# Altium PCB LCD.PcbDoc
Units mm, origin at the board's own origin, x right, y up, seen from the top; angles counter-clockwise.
Board outline 40 x 50 mm, 2 copper layers (Top Layer, Bottom Layer); 3 components, 29 nets, 23 pads, 0 vias.
Unrouted connection lines stored in the file: 1.
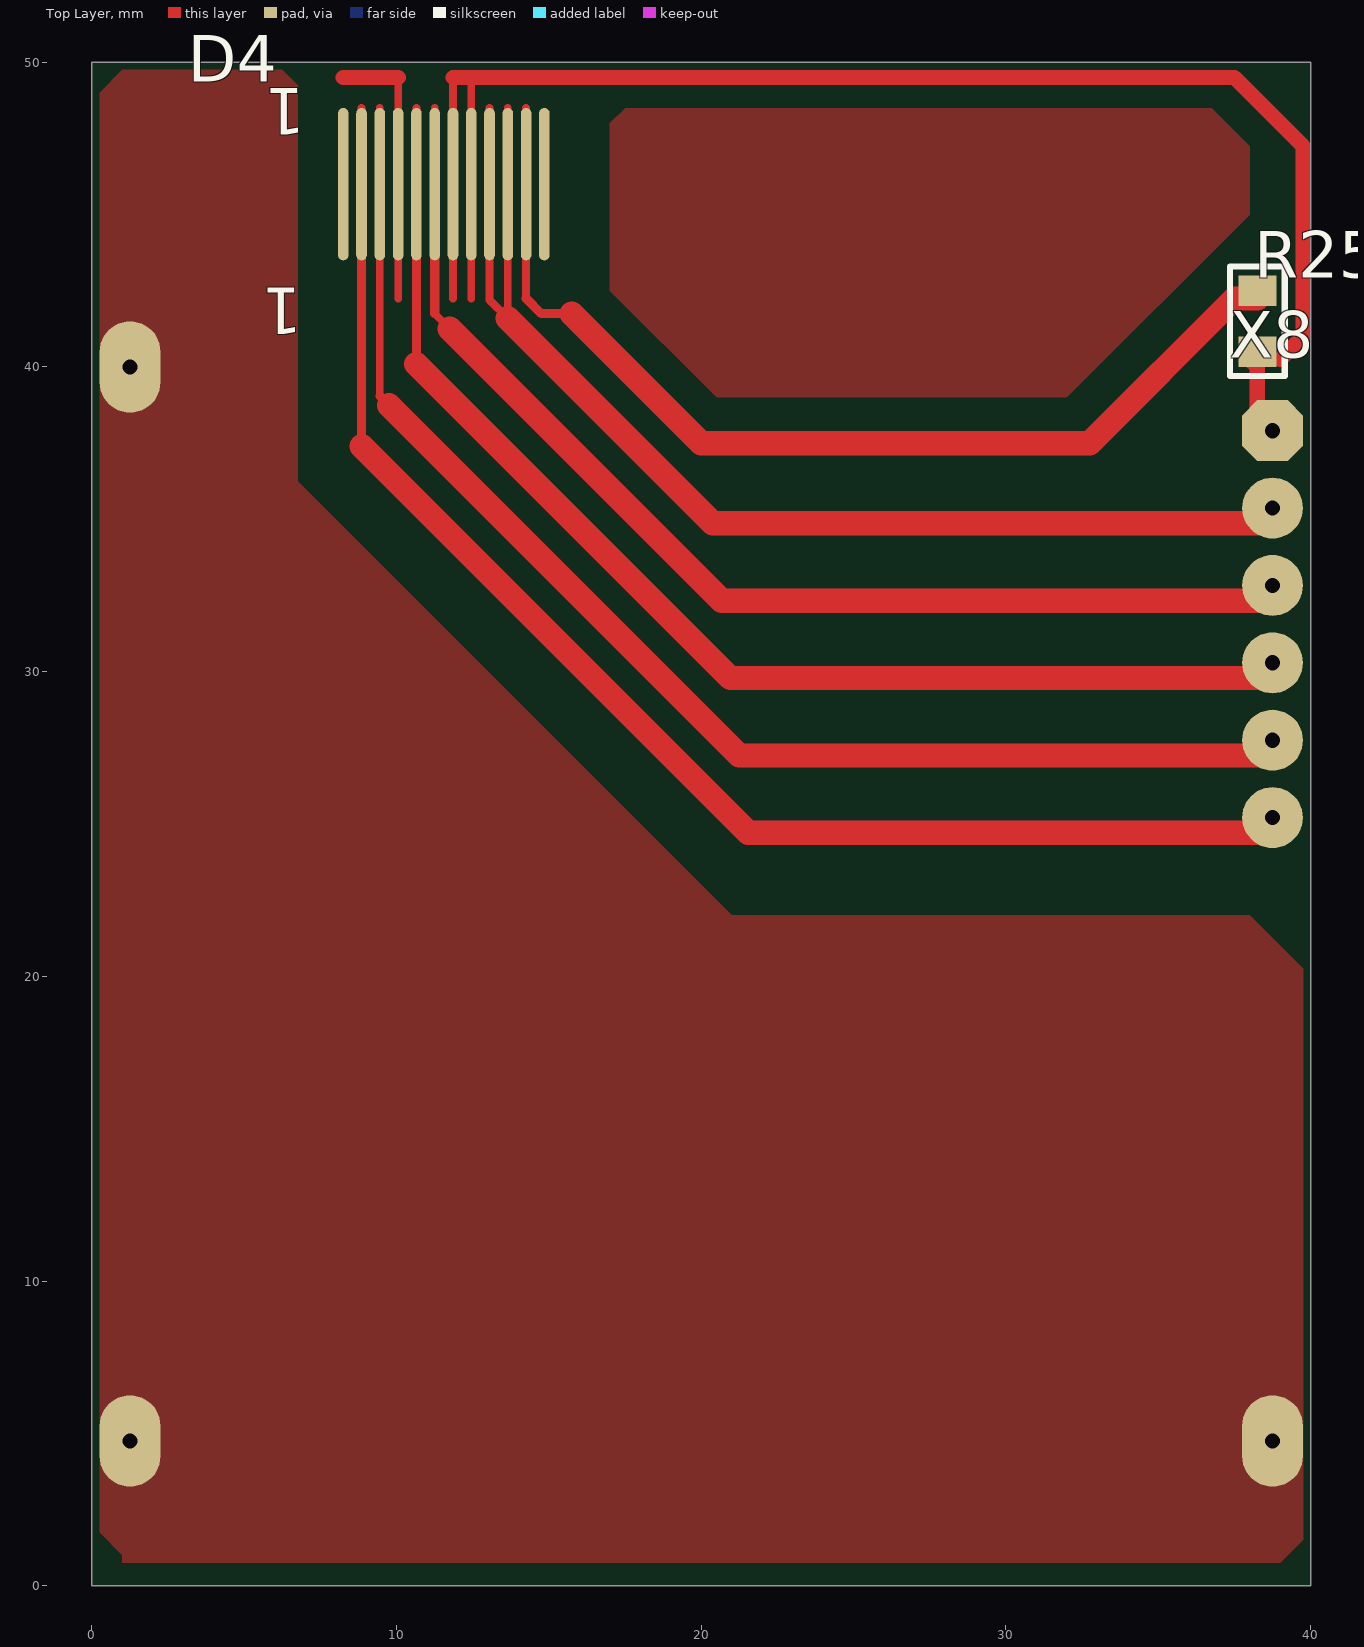
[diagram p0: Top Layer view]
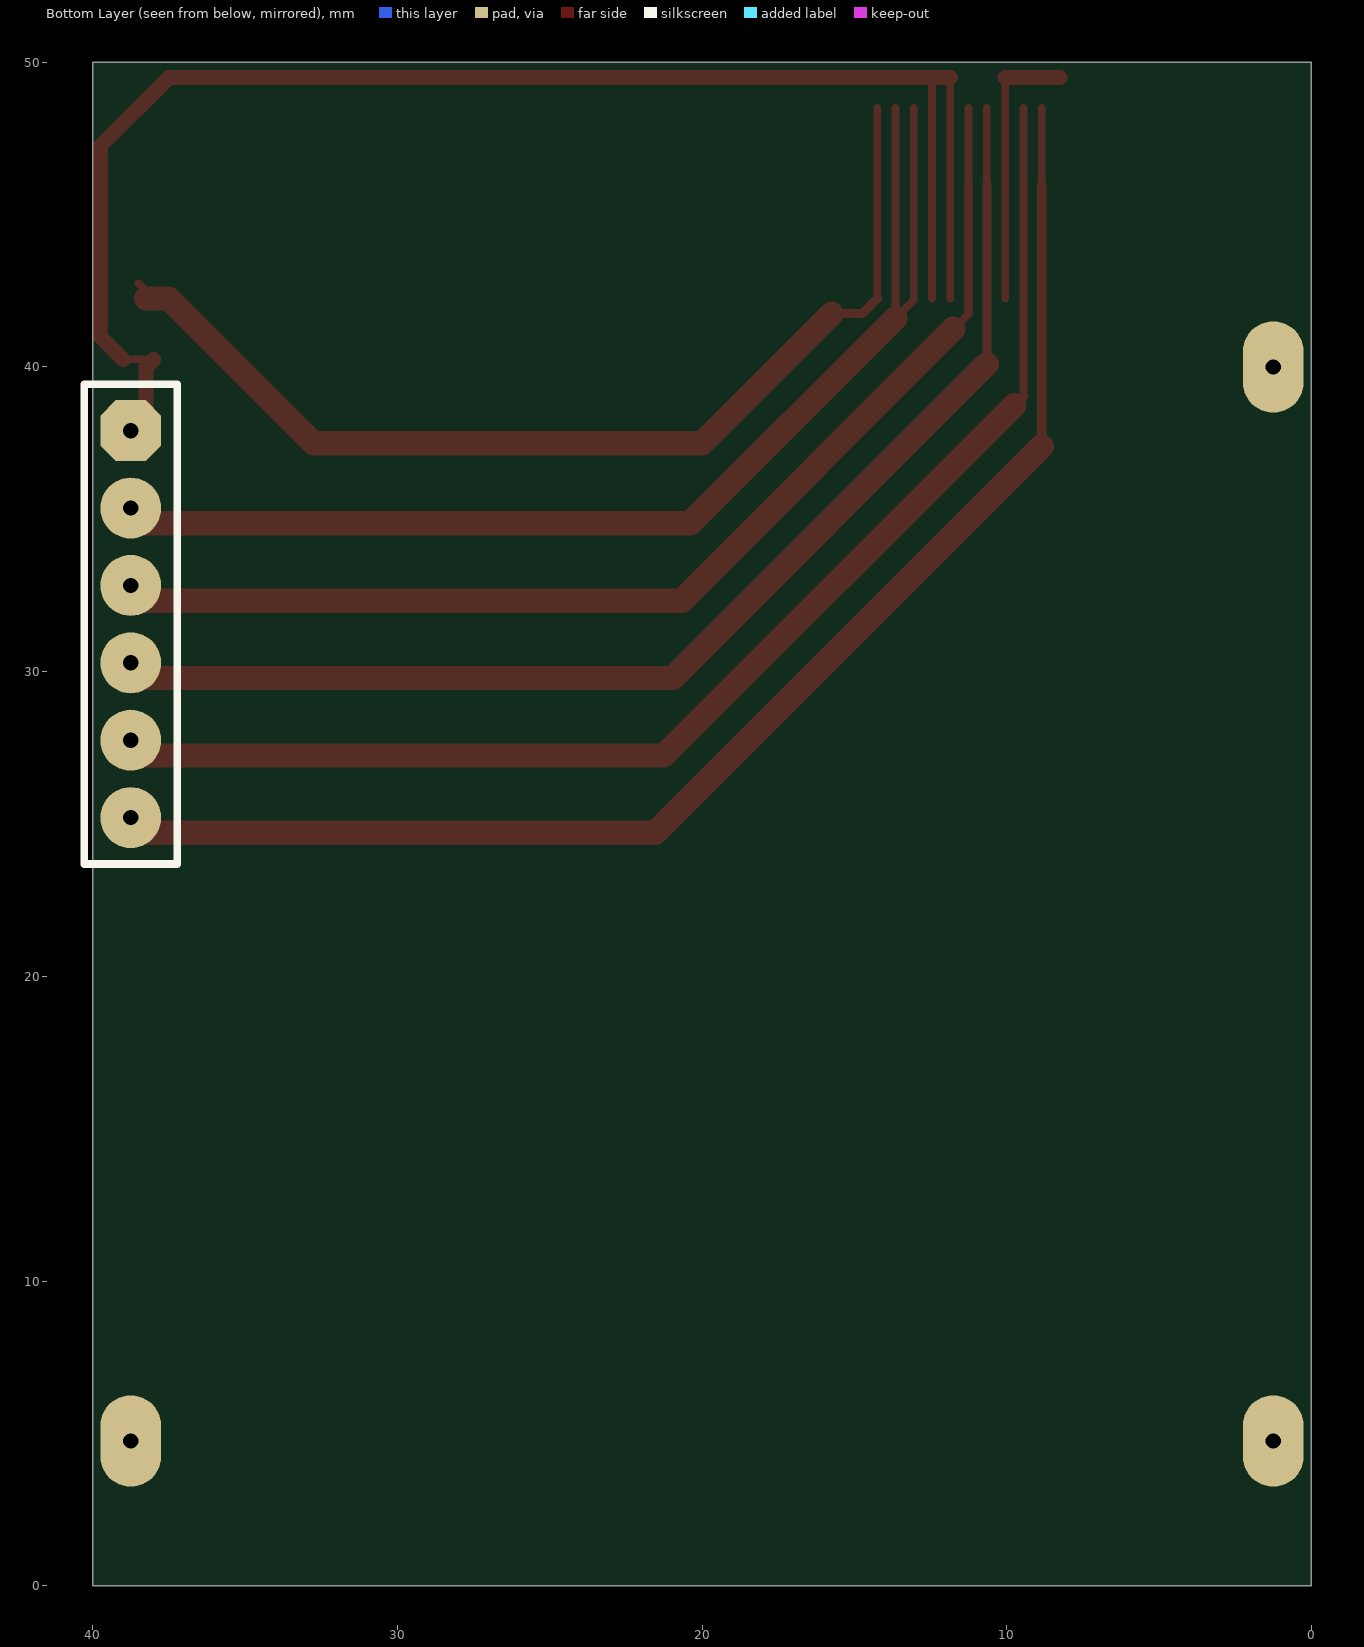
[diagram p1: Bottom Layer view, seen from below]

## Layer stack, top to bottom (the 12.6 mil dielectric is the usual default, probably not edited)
Top Solder: solder mask 0.0102, Solder Resist, Dk 3.5
Top Layer: signal copper 0.0356
Dielectric 1: dielectric 0.32, FR-4, Dk 4.8
Bottom Layer: signal copper 0.0356
Bottom Solder: solder mask 0.0102, Solder Resist, Dk 3.5

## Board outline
0,0 0,50 40,50 40,0

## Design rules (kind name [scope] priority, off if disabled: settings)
Clearance [All] p1: gap=0.1 ignorepadtopadclearanceinfootprint=FALSE
PolygonConnect [All] p1: connectstyle=Direct reliefconductorwidth=0.254 reliefentries=4 polygonreliefangle="90 Angle" airgapwidth=0.254
RoomDefinition LCD [InComponentClass('LCD')] p1: confinementstyle=ConfineIn formatcopy=TRUE lockcomponents=FALSE outline 40,30 90,30 90,100 40,100
RoutingVias [All] p1: holewidth=0.711 width=1.27 viastyle="Through Hole" minholewidth=0.711 minwidth=1.27 maxholewidth=0.711 maxwidth=1.27
SolderMaskExpansion [All] p1: expansion=0.102
Width [All] p1: maxlimit=1 minlimit=0.254 preferedwidth=0.4
30 further rules are at their usual default settings.

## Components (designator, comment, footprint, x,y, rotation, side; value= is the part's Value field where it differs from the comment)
D4 "Nokia_1616" LCD1616 20,43.5 r180 top
R25 "*" CH0805R 38.25,41.5 r90 top
X8 "*" "CON: PBS-6" 38.75,31.56 r270 top

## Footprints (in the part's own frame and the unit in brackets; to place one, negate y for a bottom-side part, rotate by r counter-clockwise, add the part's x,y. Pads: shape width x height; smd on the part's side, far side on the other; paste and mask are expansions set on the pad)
CH0805R [mm]
  rect 1x1.25 smd: 1(-1,0) 2(1,0)
  silkscreen extent -1.8,-0.9 1.8,0.9, body extent -1,-0.6 1,0.6, height 0.44
"CON: PBS-6" [mm] "PBS-6"
  oct 2x2 hole 0.5: 1(-6.35,0)
  round 2 hole 0.5: 2(-3.81,0) 3(-1.27,0) 4(1.27,0) 5(3.81,0) 6(6.35,0)
LCD1616 [mm] "LCD1616"
  oval 0.35x5 smd: 1(11.75,-2.5) 2(11.15,-2.5) 3(10.55,-2.5) 4(9.95,-2.5) 5(9.35,-2.5) 6(8.75,-2.5) 7(8.15,-2.5) 8(7.55,-2.5) 9(6.95,-2.5) 10(6.35,-2.5) 11(5.75,-2.5) 12(5.15,-2.5)
  body extent -17.1,-0.1 17.1,50.1, height 2

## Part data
D4: "MT10-T7"
R25: library part Resistor
X8: library part 6-Connector

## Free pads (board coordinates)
  oval 2x3 hole 0.5: 5(1.25,4.75) 5(1.25,40) 5(38.75,4.75)

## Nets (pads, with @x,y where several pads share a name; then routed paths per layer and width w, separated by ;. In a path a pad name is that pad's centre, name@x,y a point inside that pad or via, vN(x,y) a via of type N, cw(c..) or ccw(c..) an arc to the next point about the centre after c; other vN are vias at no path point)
ADC1: 
ADC2: 
ADC3: 
ADC4: 
BEEP: 
CS: 
CURR: 
GND: pad.5
NetC2_2: 
NetC11_1: 
NetD4_2: D4.2 X8.6 | length 46
  Top Layer w0.254: D4.2 8.85,48.5 ; X8.6@38.25,24.71 X8.6@38.5,24.71
  Top Layer w0.3: 8.85,37.4 D4.2
  Top Layer w0.8: 8.85,37.4 21.54,24.71 X8.6@38.25,24.71
NetD4_3: D4.3 X8.5 | length 43.4
  Top Layer w0.254: 9.45,39.05 D4.3 9.45,48.5 ; X8.5@38.25,27.25 X8.5@38.5,27.25
  Top Layer w0.3: 9.45,39.05 9.75,38.75
  Top Layer w0.8: 9.75,38.75 21.25,27.25 X8.5@38.25,27.25
NetD4_4: D4.4 D4.9 D4.10 X8.2 | length 50.7
  Top Layer w0.254: 10.05,42.25 D4.4 10.05,49.5 ; 13.05,48.5 D4.9 13.05,42.2 13.65,41.6 D4.10 13.65,48.5 ; X8.2@38.25,34.87 X8.2@38.5,34.87
  Top Layer w0.5: 8.25,49.5 10.05,49.5
  Top Layer w0.8: 13.65,41.6 20.38,34.87 X8.2@38.25,34.87
NetD4_5: D4.5 X8.4 | length 40.5
  Top Layer w0.254: D4.5 10.65,48.5 ; X8.4@38.25,29.79 X8.4@38.5,29.79
  Top Layer w0.3: 10.65,40.1 D4.5
  Top Layer w0.8: 10.65,40.1 20.96,29.79 X8.4@38.25,29.79
NetD4_6: D4.6 X8.3 | length 37.9
  Top Layer w0.254: 11.25,41.75 11.75,41.25 ; D4.6 11.25,48.5 ; X8.3@38.25,32.33 X8.3@38.5,32.33
  Top Layer w0.3: 11.25,41.75 D4.6
  Top Layer w0.8: 11.75,41.25 20.67,32.33 X8.3@38.25,32.33
NetD4_7: D4.7 D4.8 R25.1 X8.1 | length 54.4
  Top Layer w0.254: 11.85,42.25 D4.7 11.85,49.5 ; 12.45,42.25 D4.8 12.45,49.45 12.5,49.5 ; R25.1@38,40.25 39,40.25
  Top Layer w0.5: 11.85,49.5 12.5,49.5 37.5,49.5 39.75,47.25 39.75,41 39,40.25 ; R25.1@38,40.25 38.25,40 38.25,38.66 X8.1@39,37.91
NetD4_11: D4.11 R25.2 | length 34.9
  Top Layer w0.254: 14.25,42.25 D4.11 14.25,48.5 ; R25.2@38,42.25 R25.2 R25.2@38.5,42.75
  Top Layer w0.3: 14.25,42.25 14.75,41.75 15.75,41.75
  Top Layer w0.8: 15.75,41.75 20,37.5 32.75,37.5 37.5,42.25 38,42.25 R25.2@38.25,42.25
NetD5_11: 
NetR4_2: 
OFF: 
OPTO: 
RES: 
RST: 
SCK: 
SDA: 
SWICH: 
SWIM: 
Uout: 
VDD: 
pads on no net: D4.1 D4.12

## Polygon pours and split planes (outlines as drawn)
GND on Top Layer "GND_L01_P002" (solid, pour order 2): 17,48 17,42.5 20.5,39 32,39 38,45 38,47.25 36.75,48.5 17.5,48.5
GND on Top Layer "GND_L01_P000" (solid, pour order 0): 1,49.75 6.25,49.75 6.75,49.25 6.75,36.25 21,22 38,22 39.75,20.25 39.75,1.5 39,0.75 1,0.75 1,1 0.25,1.75 0.25,2.25 0.25,49

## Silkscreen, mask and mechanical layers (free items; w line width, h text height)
Top Overlay:
  text "1" at 7,49.15 h1.52 r180
Top Assy:
  lines w0.2: 3.1,0.05 3.1,50.05 37.1,50.05 37.1,0.05 37.1,18.55
Border:
  the board outline again, w0.2
3D view:
  lines w0.2: 3.1,0.05 37.1,0.05 37.1,50.05 3.1,50.05 3.1,0.05
Area:
  lines w0.2: 3.1,0.05 3.1,50.05 37.1,50.05 37.1,0.05 3.1,0.05
  lines w0.254: 5.1,2.55 5.1,40.05 35.1,40.05 35.1,2.55 5.1,2.55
